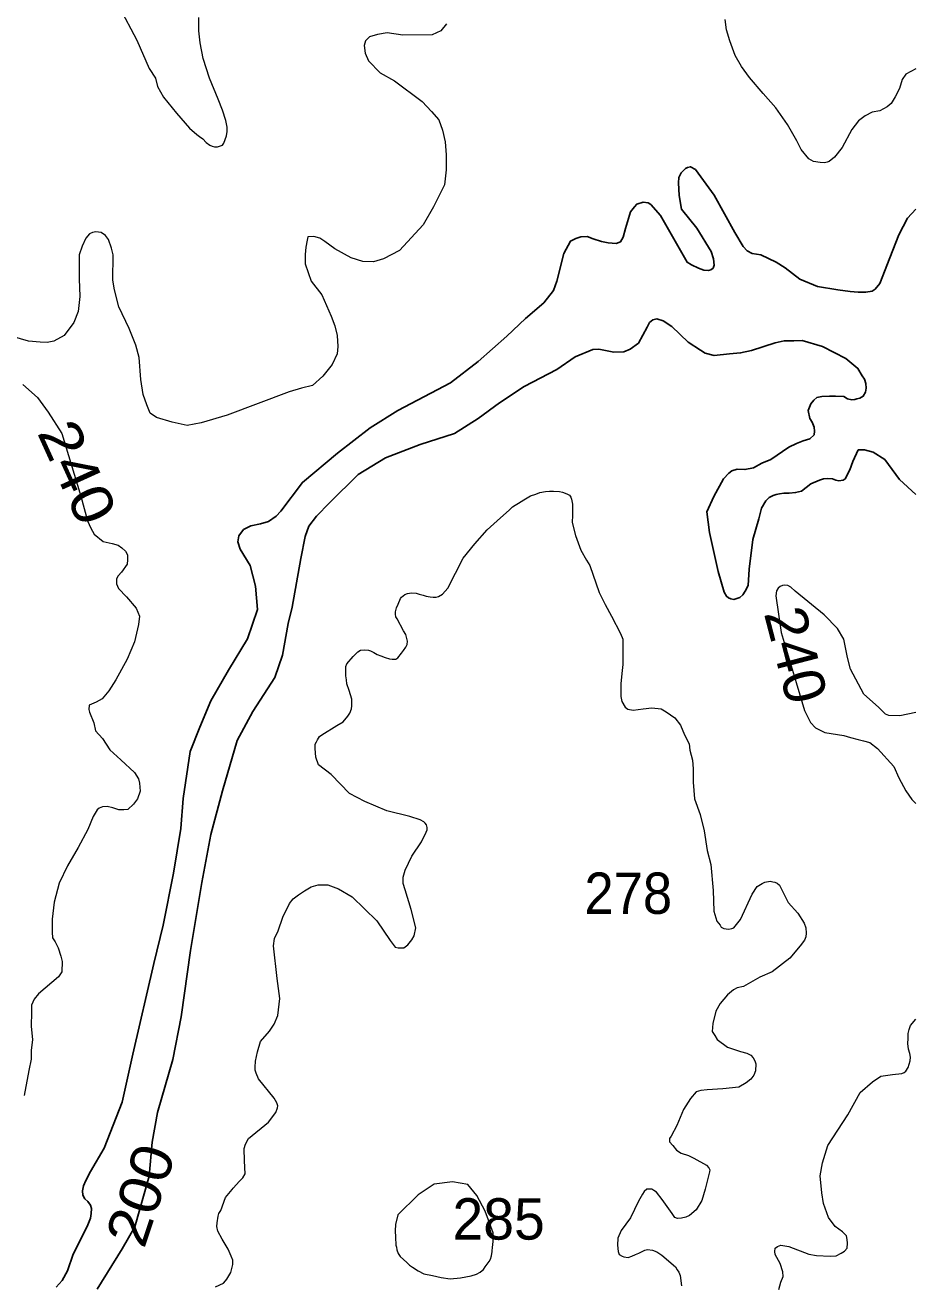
# Model space of a CAD drawing. Extents: x 445.4 to 500, y 8728.7 to 8784.
# Drawn here: x 496.556 to 500, y 8763.097 to 8767.967 of the extents above; entities that cross this region are included whole.
import ezdxf
from ezdxf.enums import TextEntityAlignment as Align

# ---------------------------------------------------------------- set-up
doc = ezdxf.new("R2010")
doc.units = 0
doc.header["$LTSCALE"] = 0.064
doc.layers.add('1', color=7, linetype='Continuous', lineweight=25)
doc.layers.add('2', color=7, linetype='Continuous', lineweight=13)
doc.layers.add('21', color=7, linetype='Continuous')
doc.layers.add('61', color=7, linetype='Continuous')

msp = doc.modelspace()

# ---------------------------------------------------------------- linework, layer by layer
at = {"layer": '1'}
for points in [[(496.7957, 8763.3182), (496.8083, 8763.3502), (496.8111, 8763.3683), (496.8124, 8763.3878), (496.8083, 8763.4004), (496.7985, 8763.4157), (496.7873, 8763.4255), (496.779, 8763.4394), (496.7776, 8763.4561), (496.7818, 8763.4756), (496.7901, 8763.4965), (496.8083, 8763.5313), (496.8615, 8763.6217), (496.9312, 8763.8), (496.973, 8763.9853), (497.0541, 8764.3362), (497.0891, 8764.4848), (497.1295, 8764.6855), (497.1574, 8764.8582), (497.1674, 8764.975), (497.1939, 8765.1561), (497.2315, 8765.2508), (497.2736, 8765.3522), (497.342, 8765.4706), (497.4159, 8765.5918), (497.4539, 8765.7056), (497.4469, 8765.7962), (497.426, 8765.8756), (497.3869, 8765.9397), (497.3785, 8765.9676), (497.3827, 8765.9912), (497.4009, 8766.0149), (497.4287, 8766.0288), (497.4664, 8766.0372), (497.4971, 8766.0456), (497.5264, 8766.0665), (497.5445, 8766.086), (497.6283, 8766.1971), (497.7636, 8766.31), (497.8905, 8766.4089), (497.9965, 8766.4757), (498.2008, 8766.5825), (498.3082, 8766.6647), (498.4184, 8766.7636), (498.4909, 8766.8319), (498.5612, 8766.8928), (498.5989, 8766.9401), (498.6114, 8766.9764), (498.6393, 8767.0836), (498.6644, 8767.131), (498.6853, 8767.1407), (498.7049, 8767.1477), (498.7286, 8767.1491), (498.7523, 8767.1394), (498.7844, 8767.1296), (498.8109, 8767.124), (498.8416, 8767.1212), (498.8583, 8767.1282), (498.8681, 8767.1463), (498.8778, 8767.1798), (498.8973, 8767.2438), (498.9122, 8767.2637), (498.9206, 8767.2735), (498.9457, 8767.2818), (498.9652, 8767.279), (498.975, 8767.2721), (499.0126, 8767.2303), (499.1158, 8767.0492), (499.1326, 8767.0394), (499.1591, 8767.0269), (499.18, 8767.0185), (499.1981, 8767.0171), (499.2079, 8767.0199), (499.2163, 8767.0269), (499.2204, 8767.038), (499.2176, 8767.0631), (499.2093, 8767.0909), (499.1535, 8767.1815), (499.0935, 8767.2553), (499.0854, 8767.3074), (499.0826, 8767.3562), (499.084, 8767.3771), (499.0924, 8767.3952), (499.1091, 8767.4119), (499.1175, 8767.4161), (499.1287, 8767.4188), (499.1482, 8767.4077), (499.2207, 8767.3088), (499.3002, 8767.1639), (499.3325, 8767.11), (499.3478, 8767.0933), (499.3674, 8767.0835), (499.4008, 8767.0779), (499.4594, 8767.0501), (499.4943, 8767.0278), (499.5515, 8766.9832), (499.6198, 8766.9553), (499.6979, 8766.9428), (499.7467, 8766.9358), (499.7774, 8766.933), (499.8067, 8766.933)], [(499.8067, 8766.933), (499.8318, 8766.9372), (499.843, 8766.9456), (499.8611, 8766.9665), (499.9001, 8767.0668), (499.9343, 8767.1554), (499.9678, 8767.2195), (500, 8767.2546)], [(500, 8766.1504), (499.9365, 8766.209), (499.8808, 8766.2859), (499.8357, 8766.315), (499.8012, 8766.323), (499.7773, 8766.323), (499.7561, 8766.2779), (499.7455, 8766.2461), (499.7272, 8766.2109), (499.7189, 8766.2067), (499.7021, 8766.204), (499.691, 8766.2067), (499.6784, 8766.2109), (499.6603, 8766.2123), (499.6436, 8766.2109), (499.6282, 8766.2067), (499.5947, 8766.1914), (499.5585, 8766.1635), (499.5348, 8766.158), (499.5097, 8766.1552), (499.4901, 8766.1552), (499.4734, 8766.1538), (499.4594, 8766.151), (499.4483, 8766.1468), (499.4329, 8766.1385), (499.4204, 8766.1259), (499.4037, 8766.0981), (499.3925, 8766.0563), (499.3697, 8765.9759), (499.3557, 8765.8616), (499.3516, 8765.799), (499.3404, 8765.7767), (499.3306, 8765.7627), (499.3195, 8765.7516), (499.2958, 8765.7446), (499.2846, 8765.7474), (499.2762, 8765.7502), (499.2679, 8765.7572), (499.2595, 8765.7725), (499.2358, 8765.8533), (499.2023, 8766.0037), (499.1925, 8766.0842), (499.219, 8766.1427), (499.2567, 8766.2109), (499.2776, 8766.2332), (499.2888, 8766.2416), (499.3097, 8766.2485), (499.339, 8766.2472), (499.3724, 8766.2541), (499.4045, 8766.2722), (499.4394, 8766.2862), (499.5091, 8766.3335), (499.5384, 8766.3475), (499.5649, 8766.3586), (499.59, 8766.3656), (499.6068, 8766.3809), (499.6081, 8766.3962), (499.6068, 8766.4115), (499.5998, 8766.431), (499.59, 8766.445), (499.5835, 8766.4752), (499.5946, 8766.5017), (499.6058, 8766.5157), (499.6169, 8766.5254), (499.6365, 8766.5296), (499.6658, 8766.531), (499.6895, 8766.531), (499.7215, 8766.5296), (499.7355, 8766.5212), (499.7522, 8766.517), (499.7648, 8766.5184), (499.7718, 8766.5212), (499.7829, 8766.524), (499.7969, 8766.531), (499.8052, 8766.5463), (499.808, 8766.5616), (499.8066, 8766.5797), (499.801, 8766.5965), (499.7927, 8766.6104), (499.7759, 8766.6382), (499.7299, 8766.6773), (499.6393, 8766.7232), (499.5612, 8766.7469), (499.5277, 8766.7455), (499.4914, 8766.7455), (499.4565, 8766.7372), (499.3645, 8766.7079), (499.3227, 8766.6982), (499.2794, 8766.6954), (499.22, 8766.6891), (499.1851, 8766.6975), (499.167, 8766.7086), (499.1196, 8766.7407), (499.0568, 8766.8006), (499.0233, 8766.8229), (498.9982, 8766.8298), (498.9829, 8766.827), (498.9703, 8766.8159), (498.9606, 8766.7978), (498.9271, 8766.7365), (498.895, 8766.7128)], [(498.895, 8766.7128), (498.8713, 8766.7031), (498.8323, 8766.7017), (498.7737, 8766.7128), (498.7514, 8766.7114), (498.683, 8766.6836), (498.6125, 8766.6337), (498.4856, 8766.5683), (498.3908, 8766.5056), (498.3071, 8766.4443), (498.2164, 8766.3871), (498.0831, 8766.3435), (497.9492, 8766.2919), (497.8432, 8766.2279), (497.733, 8766.1178), (497.6823, 8766.0668), (497.6531, 8766.0278), (497.6391, 8765.9887), (497.6224, 8765.9024), (497.5889, 8765.7143), (497.5735, 8765.6518), (497.5511, 8765.5292), (497.5219, 8765.4429), (497.4368, 8765.3105), (497.3764, 8765.1993), (497.3192, 8765.0043), (497.2746, 8764.8357), (497.2397, 8764.6492), (497.1951, 8764.3859), (497.1588, 8764.1299), (497.1267, 8763.9641), (497.068, 8763.7595), (497.0471, 8763.6453), (497.0359, 8763.5129), (496.98, 8763.3168), (496.9312, 8763.2318), (496.8349, 8763.0758)], [(496.6755, 8763.0832), (496.6992, 8763.1096), (496.7202, 8763.1472), (496.7413, 8763.2109), (496.7957, 8763.3182)]]:
    msp.add_lwpolyline(points, dxfattribs=at)
at = {"layer": '2'}
for points in [[(496.9195, 8768.0382), (496.9873, 8767.9087), (497.0351, 8767.7986), (497.0596, 8767.7614), (497.0678, 8767.7294), (497.091, 8767.6884), (497.1413, 8767.6256), (497.1912, 8767.5683), (497.2203, 8767.543), (497.23, 8767.5363), (497.2434, 8767.5266), (497.2561, 8767.5125), (497.2702, 8767.502), (497.2792, 8767.4983), (497.2881, 8767.4953), (497.2993, 8767.4953), (497.3194, 8767.502), (497.3239, 8767.5102), (497.3299, 8767.5236), (497.3351, 8767.5378), (497.3373, 8767.5549), (497.3373, 8767.572), (497.3314, 8767.5981), (497.3187, 8767.6383), (497.3021, 8767.6806), (497.2686, 8767.7617), (497.2447, 8767.8377), (497.2321, 8767.898), (497.227, 8767.9448), (497.227, 8767.9969)], [(498.1856, 8767.9721), (498.1635, 8767.9449), (498.1295, 8767.9296), (498.0168, 8767.9284), (497.9556, 8767.9369), (497.9182, 8767.9301), (497.8876, 8767.9216), (497.8723, 8767.9063), (497.8672, 8767.8876), (497.8706, 8767.8587), (497.8842, 8767.8281), (497.9284, 8767.7823), (497.9836, 8767.7515), (498.0915, 8767.6718), (498.1267, 8767.632), (498.156, 8767.6003), (498.1701, 8767.5605), (498.1807, 8767.5148), (498.1843, 8767.4648), (498.1843, 8767.4073), (498.1773, 8767.3487), (498.1351, 8767.2632), (498.0952, 8767.1941), (498.0033, 8767.0949), (497.9411, 8767.0621), (497.9024, 8767.0504), (497.8613, 8767.0516), (497.8168, 8767.0668), (497.7534, 8767.1008), (497.7147, 8767.1301), (497.6959, 8767.143), (497.6725, 8767.1488), (497.649, 8767.1477), (497.6467, 8767.1348), (497.6408, 8767.1078), (497.6384, 8767.0797), (497.6384, 8767.0434), (497.6619, 8766.9766), (497.703, 8766.9227), (497.7394, 8766.841), (497.7535, 8766.8035), (497.7628, 8766.766), (497.7652, 8766.7238), (497.7628, 8766.6945), (497.7429, 8766.6535), (497.7065, 8766.609), (497.6666, 8766.5726), (497.624, 8766.5623), (497.577, 8766.5482), (497.3377, 8766.458), (497.237, 8766.4276), (497.1831, 8766.4171), (497.1244, 8766.43)], [(500, 8767.798), (499.9615, 8767.7765), (499.9469, 8767.7566), (499.9363, 8767.7215), (499.9204, 8767.6897), (499.9051, 8767.6632), (499.8886, 8767.65), (499.8607, 8767.6354), (499.8312, 8767.6303), (499.8041, 8767.6157), (499.7782, 8767.5971), (499.753, 8767.5634), (499.7152, 8767.4932), (499.686, 8767.4554), (499.6648, 8767.4395), (499.6575, 8767.4369), (499.6469, 8767.4342), (499.6303, 8767.4349), (499.6038, 8767.4389), (499.5859, 8767.4495), (499.5567, 8767.4859), (499.5397, 8767.5196), (499.5039, 8767.5826), (499.4581, 8767.6465), (499.4097, 8767.7021), (499.3567, 8767.7643), (499.3266, 8767.8073), (499.3014, 8767.8497), (499.2809, 8767.906), (499.2676, 8767.9484), (499.2629, 8767.9888)], [(497.1244, 8766.43), (497.0634, 8766.4487), (497.0399, 8766.4651), (497.0259, 8766.4979), (497.0118, 8766.5378), (497.0036, 8766.5952), (496.9966, 8766.6804), (496.9837, 8766.7285), (496.9579, 8766.7929), (496.918, 8766.8773), (496.9016, 8766.9429), (496.8945, 8766.9801), (496.8968, 8767.0785), (496.8898, 8767.1032), (496.8781, 8767.1371), (496.8663, 8767.1524), (496.8499, 8767.1641), (496.8288, 8767.1664), (496.817, 8767.1641), (496.8053, 8767.1594), (496.7912, 8767.143), (496.776, 8767.1114), (496.7654, 8767.0785), (496.7654, 8766.9848), (496.7678, 8766.9168), (496.7604, 8766.8585), (496.744, 8766.8163), (496.7064, 8766.7659), (496.6666, 8766.7437), (496.6407, 8766.739), (496.6138, 8766.7402), (496.5692, 8766.7437), (496.4765, 8766.7706)], [(496.5468, 8766.5767), (496.6031, 8766.5263), (496.6453, 8766.4689), (496.6984, 8766.3862), (496.7711, 8766.1448), (496.797, 8766.0492), (496.8099, 8766.0199), (496.8228, 8765.9976), (496.858, 8765.9683), (496.892, 8765.9613), (496.9155, 8765.9542), (496.9296, 8765.9449), (496.9436, 8765.932), (496.9518, 8765.9167), (496.9518, 8765.898), (496.9507, 8765.8816), (496.9283, 8765.8504), (496.9154, 8765.8363), (496.9096, 8765.8246), (496.9096, 8765.8047), (496.9166, 8765.7871), (496.9483, 8765.7543), (496.9847, 8765.7109), (496.9976, 8765.6804), (496.994, 8765.6476), (496.9788, 8765.5808), (496.9506, 8765.5134), (496.906, 8765.4337), (496.879, 8765.3915), (496.8544, 8765.3599), (496.8309, 8765.347), (496.8039, 8765.3352), (496.8039, 8765.3352), (496.8016, 8765.3188), (496.8051, 8765.3083), (496.8215, 8765.2673), (496.8274, 8765.2356), (496.8556, 8765.2063), (496.884, 8765.1632), (496.9262, 8765.1245), (496.979, 8765.0753), (496.9943, 8765.0507), (496.9978, 8765.0331), (497.0001, 8765.0027)], [(498.0829, 8764.8922), (498.0438, 8764.9047), (497.955, 8764.9271), (497.869, 8764.9634), (497.8098, 8764.994), (497.7392, 8765.0673), (497.6909, 8765.1043), (497.6797, 8765.1337), (497.6776, 8765.1684), (497.6776, 8765.1851), (497.6825, 8765.1942), (497.6867, 8765.2012), (497.6902, 8765.2082), (497.6944, 8765.2138), (497.7027, 8765.2207), (497.7615, 8765.2564), (497.7859, 8765.271), (497.8041, 8765.2927), (497.8111, 8765.3052), (497.8174, 8765.3213), (497.8188, 8765.3325), (497.8195, 8765.3583), (497.8085, 8765.3917), (497.7994, 8765.4175), (497.798, 8765.4336), (497.7966, 8765.449), (497.7959, 8765.4629), (497.7959, 8765.4755), (497.7966, 8765.4853), (497.8001, 8765.4951), (497.8246, 8765.5244), (497.8428, 8765.5425), (497.8526, 8765.5481), (497.8701, 8765.5495), (497.8833, 8765.5481), (497.8917, 8765.546), (497.9043, 8765.539), (497.9176, 8765.5321), (497.9316, 8765.5258), (497.9477, 8765.5195), (497.9644, 8765.5146), (497.9756, 8765.5132), (497.9896, 8765.5132), (497.9966, 8765.5188), (498.0109, 8765.5367), (498.0193, 8765.5472), (498.0277, 8765.5597), (498.0333, 8765.5702), (498.034, 8765.5828), (498.0284, 8765.6093), (498.0186, 8765.6233), (497.9941, 8765.6701), (497.9892, 8765.677), (497.9878, 8765.6875), (497.9885, 8765.6973), (497.992, 8765.7127), (497.9983, 8765.7266), (498.0068, 8765.748), (498.0117, 8765.7536), (498.0242, 8765.7634), (498.0347, 8765.7676), (498.0501, 8765.7704), (498.0676, 8765.7683), (498.0802, 8765.7648), (498.0955, 8765.7606), (498.106, 8765.7578), (498.1221, 8765.7543), (498.134, 8765.7536), (498.1459, 8765.7536), (498.1543, 8765.7557), (498.1697, 8765.7655), (498.1906, 8765.7885), (498.2496, 8765.9042), (498.295, 8765.9593), (498.3426, 8766.0138), (498.3817, 8766.0487), (498.4288, 8766.0912), (498.4407, 8766.1024), (498.4512, 8766.11), (498.4638, 8766.1177), (498.4848, 8766.1296), (498.5099, 8766.145), (498.5302, 8766.1519), (498.5463, 8766.1582), (498.5687, 8766.1617), (498.5834, 8766.1638), (498.5987, 8766.1638), (498.6218, 8766.1624), (498.6344, 8766.1596), (498.6512, 8766.1526), (498.6603, 8766.1478), (498.6663, 8766.1405), (498.6684, 8766.1321), (498.6719, 8766.1132), (498.6719, 8766.0706), (498.6712, 8766.042), (498.6838, 8765.9917), (498.7047, 8765.9351), (498.7272, 8765.8962), (498.7391, 8765.8759), (498.7761, 8765.7711)], [(500, 8765.3076), (499.9386, 8765.294), (499.8952, 8765.2961), (499.8828, 8765.3002), (499.8555, 8765.3283), (499.7993, 8765.3778), (499.7473, 8765.4752), (499.7362, 8765.5203), (499.7214, 8765.5905), (499.6974, 8765.6317), (499.6462, 8765.6854), (499.5331, 8765.7767), (499.5171, 8765.7927), (499.5048, 8765.7989), (499.4938, 8765.8001), (499.4839, 8765.7989), (499.4753, 8765.7952), (499.4679, 8765.7878), (499.4617, 8765.778), (499.4581, 8765.7583), (499.479, 8765.6169), (499.538, 8765.4233), (499.57, 8765.3151), (499.5922, 8765.2683), (499.6119, 8765.2474), (499.6488, 8765.2302), (499.7215, 8765.2179), (499.7473, 8765.2105), (499.7769, 8765.2032), (499.7978, 8765.197), (499.8228, 8765.1912), (499.8524, 8765.1678), (499.9152, 8765.0978), (499.9349, 8765.0547), (499.962, 8765.0043), (499.9841, 8764.9699), (500, 8764.9555)], [(498.7761, 8765.7711), (498.7985, 8765.7244), (498.8232, 8765.6798), (498.8581, 8765.6128), (498.8665, 8765.5904), (498.8665, 8765.5639), (498.8665, 8765.4927), (498.8637, 8765.4579), (498.8588, 8765.4181), (498.8588, 8765.3692), (498.863, 8765.3497), (498.8756, 8765.328), (498.8868, 8765.3203), (498.9071, 8765.3161), (498.9455, 8765.321), (498.9798, 8765.3252), (499.0148, 8765.321), (499.0353, 8765.31), (499.0688, 8765.287), (499.0898, 8765.2577), (499.1052, 8765.2206), (499.1234, 8765.1857), (499.1262, 8765.162), (499.1367, 8765.1222), (499.1387, 8765.0887), (499.1388, 8765.037), (499.1444, 8764.9735), (499.1667, 8764.912), (499.1821, 8764.8499), (499.1934, 8764.7733), (499.2074, 8764.7195), (499.2168, 8764.618), (499.2193, 8764.5379), (499.231, 8764.4992), (499.2439, 8764.4849), (499.2478, 8764.4772), (499.2581, 8764.472), (499.2672, 8764.4707), (499.2775, 8764.4682), (499.2892, 8764.472), (499.2969, 8764.4746), (499.3215, 8764.5056), (499.3668, 8764.6038), (499.3869, 8764.6339), (499.406, 8764.6451), (499.4158, 8764.6503), (499.4362, 8764.6543), (499.4467, 8764.6523), (499.4552, 8764.6503), (499.4644, 8764.6464), (499.473, 8764.6385), (499.5064, 8764.5723), (499.5432, 8764.5309), (499.5682, 8764.4916), (499.5749, 8764.4741), (499.5756, 8764.4537), (499.5743, 8764.4386), (499.569, 8764.4262), (499.5533, 8764.4045), (499.5126, 8764.3566), (499.4443, 8764.3042), (499.3973, 8764.2827), (499.3342, 8764.2473), (499.3086, 8764.2414), (499.2955, 8764.2335), (499.2712, 8764.2151), (499.243, 8764.181), (499.2265, 8764.1517), (499.2152, 8764.1041), (499.2123, 8764.0732), (499.2223, 8764.0569), (499.2323, 8764.0419), (499.2712, 8764.0118), (499.3226, 8763.9955), (499.3465, 8763.9893), (499.3615, 8763.9818), (499.3715, 8763.9705), (499.3778, 8763.9592), (499.3816, 8763.9479), (499.3803, 8763.9204), (499.3741, 8763.9041), (499.3615, 8763.8878), (499.3439, 8763.874), (499.3151, 8763.8577), (499.2536, 8763.8515), (499.1934, 8763.8477), (499.1684, 8763.844), (499.1508, 8763.8389), (499.1282, 8763.8139), (499.1019, 8763.7713), (499.0755, 8763.7087), (499.0543, 8763.6676), (499.048, 8763.6589), (499.048, 8763.6589), (499.048, 8763.6463), (499.0605, 8763.6313), (499.0743, 8763.6138), (499.0931, 8763.6025), (499.1207, 8763.5925), (499.1421, 8763.5824), (499.191, 8763.5561)], [(497.0001, 8765.0027), (496.9907, 8764.9734), (496.9755, 8764.9523), (496.9532, 8764.9323), (496.938, 8764.93), (496.918, 8764.93), (496.8945, 8764.9382), (496.8734, 8764.9429), (496.8547, 8764.9417), (496.8418, 8764.937), (496.8347, 8764.93), (496.8195, 8764.9042), (496.7983, 8764.855), (496.7605, 8764.7849), (496.7194, 8764.7134), (496.6877, 8764.6466), (496.6678, 8764.5728), (496.6608, 8764.5072), (496.6608, 8764.457), (496.6619, 8764.4347), (496.6725, 8764.4195), (496.6831, 8764.3972), (496.6936, 8764.3644), (496.6995, 8764.3433), (496.6983, 8764.3035), (496.6854, 8764.2847), (496.608, 8764.2191), (496.5904, 8764.198), (496.581, 8764.1746), (496.581, 8764.1476), (496.5798, 8764.0941), (496.5845, 8764.0402), (496.5786, 8764.0004), (496.5798, 8763.9664), (496.5704, 8763.9219), (496.5528, 8763.8246)], [(497.2926, 8763.0843), (497.3233, 8763.0987), (497.3306, 8763.1075), (497.3354, 8763.1148), (497.3394, 8763.1204), (497.3507, 8763.1405), (497.3595, 8763.171), (497.3587, 8763.1887), (497.3523, 8763.2039), (497.341, 8763.2305), (497.3177, 8763.2698), (497.3007, 8763.3009), (497.2975, 8763.3178), (497.2991, 8763.3331), (497.3023, 8763.3588), (497.3048, 8763.3684), (497.312, 8763.3797), (497.3305, 8763.4303), (497.3562, 8763.4616), (497.3603, 8763.4672), (497.3854, 8763.4943), (497.3982, 8763.5064), (497.4071, 8763.5217), (497.4039, 8763.5723), (497.4023, 8763.6197), (497.4079, 8763.6373), (497.4192, 8763.659), (497.4972, 8763.7225), (497.5248, 8763.7593), (497.5312, 8763.7769), (497.5328, 8763.7858), (497.5296, 8763.797), (497.5191, 8763.8147), (497.458, 8763.8894), (497.4491, 8763.9119), (497.4459, 8763.9239), (497.4459, 8763.9344), (497.4467, 8763.9577), (497.4539, 8763.9945), (497.466, 8764.0347), (497.5006, 8764.0748), (497.5191, 8764.1013), (497.5327, 8764.1343), (497.5408, 8764.2002), (497.5303, 8764.2779), (497.5159, 8764.4049), (497.5207, 8764.433), (497.5344, 8764.4627), (497.5521, 8764.5147), (497.5778, 8764.5678), (497.5923, 8764.5862), (497.6132, 8764.6015), (497.6365, 8764.6176), (497.6615, 8764.6328), (497.6888, 8764.6409), (497.727, 8764.6398), (497.7678, 8764.6251), (497.8201, 8764.5941), (497.9164, 8764.5012), (497.967, 8764.4245), (497.987, 8764.3995), (497.9985, 8764.3963), (498.0115, 8764.3963), (498.0197, 8764.3963), (498.0197, 8764.3963), (498.036, 8764.4077), (498.0507, 8764.4273), (498.0605, 8764.4436), (498.067, 8764.4745), (498.0491, 8764.5447), (498.0249, 8764.6206), (498.0183, 8764.645), (498.0183, 8764.6695), (498.0249, 8764.6972), (498.051, 8764.751), (498.0886, 8764.8065), (498.1067, 8764.8447), (498.1102, 8764.8538), (498.1102, 8764.8621), (498.1074, 8764.8719), (498.1025, 8764.8796), (498.0976, 8764.8845), (498.0829, 8764.8922)], [(499.6624, 8763.3538), (499.6436, 8763.4077), (499.636, 8763.449), (499.6307, 8763.515), (499.6395, 8763.5651), (499.6596, 8763.6315), (499.7374, 8763.7505), (499.7842, 8763.8366), (499.8331, 8763.878), (499.8644, 8763.9005), (499.9096, 8763.9068), (499.9462, 8763.9108), (499.955, 8763.9144), (499.9608, 8763.9195), (499.971, 8763.9341), (499.9783, 8763.9589), (499.9791, 8763.9735), (499.9769, 8763.988), (499.9718, 8764.0048), (499.9696, 8764.026), (499.9703, 8764.0464), (499.9703, 8764.0646), (499.9739, 8764.0807), (499.9791, 8764.0967), (500, 8764.1209)], [(499.191, 8763.5561), (499.1997, 8763.5449), (499.2035, 8763.5373), (499.2023, 8763.5298), (499.1859, 8763.4634), (499.1722, 8763.4196), (499.1508, 8763.3832), (499.1245, 8763.3607), (499.1107, 8763.3544), (499.0944, 8763.3507), (499.0781, 8763.3494), (499.0681, 8763.3532), (499.058, 8763.3682), (499.0191, 8763.4233), (498.9978, 8763.4509), (498.9865, 8763.4572), (498.979, 8763.4634), (498.9665, 8763.4634), (498.9602, 8763.4622), (498.9502, 8763.4534), (498.9426, 8763.4434), (498.9276, 8763.4158), (498.8971, 8763.3524), (498.8607, 8763.3023), (498.8482, 8763.2735), (498.8469, 8763.2459), (498.8494, 8763.2221), (498.8532, 8763.2096), (498.8645, 8763.2033), (498.8708, 8763.2008), (498.8883, 8763.1983), (498.9021, 8763.2033), (498.9159, 8763.2096), (498.9285, 8763.2146), (498.9423, 8763.2221), (498.9523, 8763.2271), (498.9623, 8763.2296), (498.9824, 8763.2271), (498.9987, 8763.2209), (499.0175, 8763.2071), (499.0702, 8763.162), (499.0777, 8763.1507), (499.084, 8763.1419), (499.089, 8763.1294), (499.094, 8763.0893)], [(499.4702, 8763.0748), (499.4778, 8763.1036), (499.4865, 8763.1249), (499.4853, 8763.1425), (499.4752, 8763.1751), (499.4567, 8763.2097), (499.4554, 8763.221), (499.4567, 8763.2348), (499.4655, 8763.2411), (499.478, 8763.2461), (499.5094, 8763.2411), (499.5859, 8763.211), (499.616, 8763.206), (499.6686, 8763.2035), (499.6925, 8763.2047), (499.7113, 8763.2148), (499.7238, 8763.2235), (499.7351, 8763.2348), (499.7364, 8763.2536), (499.7351, 8763.2686), (499.7326, 8763.2824), (499.7163, 8763.2974), (499.6887, 8763.3187), (499.6624, 8763.3538)]]:
    msp.add_lwpolyline(points, dxfattribs=at)
msp.add_lwpolyline([(498.3349, 8763.3773), (498.3029, 8763.4387), (498.2674, 8763.4803), (498.2091, 8763.4907), (498.1382, 8763.4824), (498.0757, 8763.4408), (497.9965, 8763.3637), (497.9881, 8763.3263), (497.9869, 8763.3019), (497.9878, 8763.2771), (497.9897, 8763.2466), (497.9917, 8763.2379), (497.9929, 8763.2276), (497.9981, 8763.2143), (498.0063, 8763.2029), (498.0321, 8763.1789), (498.0419, 8763.1683), (498.0542, 8763.1604), (498.0752, 8763.1462), (498.098, 8763.1357), (498.1306, 8763.1293), (498.1643, 8763.1207), (498.1994, 8763.1163), (498.2398, 8763.1192), (498.2801, 8763.1279), (498.3018, 8763.134), (498.3151, 8763.1417), (498.3235, 8763.1477), (498.3289, 8763.1525), (498.3349, 8763.1625), (498.3503, 8763.1828), (498.3558, 8763.1921), (498.3599, 8763.2054), (498.3614, 8763.2221), (498.3632, 8763.2395), (498.3645, 8763.2456), (498.3673, 8763.279), (498.3654, 8763.2943), (498.3521, 8763.3325)], close=True, dxfattribs=at)

# ---------------------------------------------------------------- texts
at = {"layer": '21', "width": 0.95}
msp.add_text('278', height=0.16, dxfattribs=at).set_placement((498.7186, 8764.528))
at = {"layer": '21'}
msp.add_text('285', height=0.16, dxfattribs=at).set_placement((498.2083, 8763.2676))
at = {"layer": '61'}
for s, rotation, width, p in [('240', 294.432, 1.15, (496.6854, 8766.2039)), ('240', 284.602, 1.05, (499.4592, 8765.5101)), ('200', 71.577, 1.1, (497.0776, 8763.4149))]:
    msp.add_text(s, height=0.16, rotation=rotation, dxfattribs=dict(at, width=width)).set_placement(p, align=Align.CENTER)

doc.saveas('drawing.dxf')
